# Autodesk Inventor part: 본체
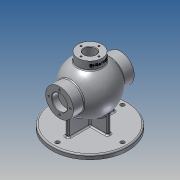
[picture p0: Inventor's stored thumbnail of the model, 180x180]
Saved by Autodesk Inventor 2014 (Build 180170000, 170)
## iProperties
Created: 2020-08
Part Number: 본체
Material: 알루미늄 6061
Document SubType Name: Modeling
Designer: kb542
Density: 2.71 g/cm^3
Appearance: 알루미늄 - 평지
Mass: 1.8289e+06 g
Surface Area: 137041 cm^2
Volume: 674872 cm^3
Author: kb542
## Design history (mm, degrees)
sketch "스케치1"
  geometry: L1 (0, 1783.933)-(0, 0); L2 (0, 0)-(680, 0); L3 (680, 0)-(680, 310); L4 (680, 310)-(442.154, 310); L5 (392.779, 175)-(680, 175); A1 r 540 centre (0, 0) between (442.154, 310) and (0, 540); A2 r 430 centre (0, 0) between (392.779, 175) and (0, 430); 1 further point
  constraints: 10 end point, 4 point on circle, 3 coincident, 3 perpendicular, 3 point on line, 2 centre point, 1 parallel, 1 vertical
  dimensions: "d0" = 1360 diameter of L3 L1; "d1" = 620 diameter of L4 L2; "d2" = 1080 diameter of A1; "d4" = 860 diameter of A2; "d5" = 350 diameter of L5 L2
revolve "회전1" sketch "스케치1" stored, may be unused: angle "d6" = 90 deg
node "작업 평면1"
fillet "모깎기1" dims "d42" = 30
chamfer "모따기1" distance "d52" = 10; stored, may be unused: second distance "d53" = 3.175, angle "d54" = 45 deg
chamfer "모따기2" distance "d55" = 10; stored, may be unused: second distance "d56" = 3.175, angle "d57" = 45 deg
node "작업 평면3"
node "작업 평면5"
sketch "스케치15"
  geometry: C1 r 850 at (0, 0); 1 further point
  constraints: 1 centre point, 1 coincident
  dimensions: "d99" = 1700 diameter of C1
extrude "돌출7" join sketch "스케치15" distance "d100" = 100; taper "d101" = 0 deg
sketch "스케치16"
  geometry: L1 (-40, 430)-(40, 430); L2 (40, 430)-(40, -430); L3 (40, -430)-(-40, -430); L4 (-40, -430)-(-40, 430); L5 (-520, 40)-(520, 40); L6 (520, 40)-(520, -40); L7 (520, -40)-(-520, -40); L8 (-520, -40)-(-520, 40); C1 r 850 at (0, 0) reference; 4 further points
  constraints: 16 end point, 4 midpoint, 4 parallel, 2 horizontal, 2 horizontal alignment, 2 perpendicular, 2 vertical alignment
  dimensions: "d102" = 80 distance of L2.end L3.end; "d103" = 860 distance between parallel lines of L3 L1; "d104" = 80 distance between parallel lines of L7 L5; "d105" = 1040 distance between parallel lines of L6 L8
extrude "돌출8" join sketch "스케치16" stored distance "d106" = 100; taper "d107" = 0 deg
node "작업 평면6"
sketch "스케치17"
  geometry: C1 r 270 at (0, 0); 1 further point
  constraints: 1 centre point, 1 coincident
  dimensions: "d109" = 540 diameter of C1
extrude "돌출9" join sketch "스케치17" stored distance "d110" = 100; taper "d111" = 0 deg
sketch "스케치18"
  geometry: C1 r 130 at (0, 0); 1 further point
  constraints: 1 centre point, 1 coincident
  dimensions: "d112" = 260 diameter of C1
extrude "돌출10" cut sketch "스케치18" stored distance "d113" = 100; taper "d114" = 0 deg
fillet "모깎기4" dims "d115" = 30
fillet "모깎기5" dims "d116" = 30
fillet "모깎기6" dims "d117" = 30
sketch "스케치19"
  geometry: C1 r 185 at (0, 0) reference; A1 r 240 centre (0, 0) between (0, 240) and (240, 0); 2 further points
  constraints: 4 point on circle, 1 centre point, 1 coincident
  dimensions: "d118" = 480 diameter of A1
hole "구멍6" sketch "스케치19" at (0, 240), (240, 0), (0, -240), (-240, 0) diameter "d119" = 40.386; stored, may be unused: countersink angle "d123" = 82 deg, drill point angle "d125" = 118 deg; dims "d120" = 120, "d121" = 3.0226, "d122" = 6.35, "d124" = 150
sketch "스케치21"
  geometry: C1 r 130 at (0, 0) reference; A1 r 200 centre (0, 0) between (0, 200) and (200, 0); 2 further points
  constraints: 4 point on circle, 1 centre point, 1 coincident
  dimensions: "d134" = 400 diameter of A1
hole "구멍8" sketch "스케치21" at (0, 200), (200, 0), (0, -200), (-200, 0) diameter "d135" = 40.386; stored, may be unused: countersink angle "d139" = 82 deg, drill point angle "d141" = 118 deg; dims "d136" = 304.8, "d137" = 3.0226, "d138" = 6.35, "d140" = 381
fillet "모깎기7" dims "d142" = 30
node "작업 평면8"
sketch "스케치24"
  geometry: L1 (270, 650)-(-270, 650) reference; L2 (-270, 650)-(-270, 484.665) reference; 2 further points
  constraints: 1 other
  dimensions: "d146" = 90 distance from line of point (0, 560) L1; "d147" = 270 distance from line of point (0, 560) L2
feature "엠보싱2" sketch "스케치24" dims "d148" = 5, "d149" = 0
chamfer "모따기4" distance "d150" = 10; stored, may be unused: second distance "d151" = 3.175, angle "d152" = 45 deg
node "작업 평면9"
sketch "스케치25"
  geometry: C1 r 185 at (0, 0); 1 further point
  constraints: 1 centre point, 1 coincident
  dimensions: "d154" = 370 diameter of C1
extrude "돌출11" join sketch "스케치25" distance "d155" = 17.5; taper "d156" = 0 deg
sketch "스케치26" dims "d158" = 1450
  geometry: C1 r 820 at (0, 0) reference; C2 r 45 at (0, 725); C3 r 45 at (-725, 0); C4 r 45 at (0, -725); C5 r 45 at (725, 0); 1 further point
  constraints: 4 centre point, 1 coincident, 1 vertical alignment, 11 other
  dimensions: "d157" = 90 diameter of C2; "d161" = 360 deg dimension on point (0, 0) C2.centre (derived)
extrude "돌출12" cut sketch "스케치26" stored distance "d163" = 17.5; taper "d164" = 0 deg
node "솔리드1"
mirror "대칭1"
mirror "대칭3"
other parameters: "d24" = -2159, "d61" = -685.8, "d145" = -275
